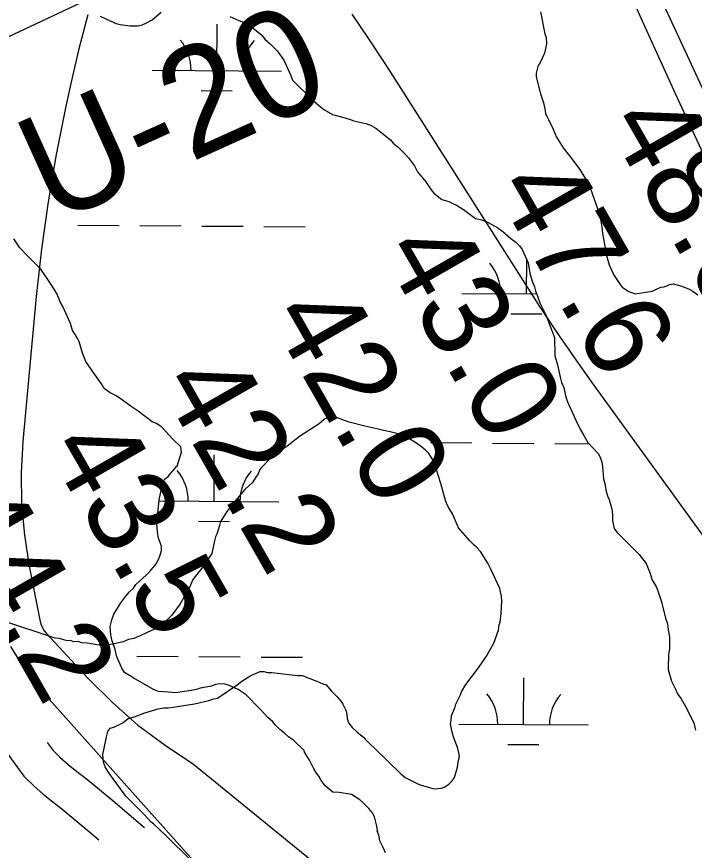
# Model space of a CAD drawing. Extents: x 3172231 to 3210228, y 940198 to 965780.
# Drawn here: x 3188355 to 3188879, y 950157 to 950801 of the extents above; entities that cross this region are included whole.
import ezdxf

# ---------------------------------------------------------------- set-up
doc = ezdxf.new("R2010")
doc.units = 0
for name, color, linetype in [('V-RIVR-RANG', 7, 'Continuous'), ('V-RIVR-RANG-IDEN', 7, 'Continuous'), ('V-ROAD-CNTR', 7, 'Continuous'), ('V-SITE-VEGE', 7, 'Continuous'), ('V-TOPO-MAJR', 7, 'Continuous'), ('V-TOPO-MINR', 7, 'Continuous'), ('V-WETL-SWMP', 7, 'Continuous')]:
    doc.layers.add(name, color=color, linetype=linetype)

msp = doc.modelspace()

# ---------------------------------------------------------------- linework, layer by layer
at = {"layer": 'V-RIVR-RANG'}
msp.add_line((3188285.159, 950755.845), (3189462.372, 951307.359), dxfattribs=at)
at = {"layer": 'V-ROAD-CNTR'}
for points in [[(3188379.01, 950240.383), (3188383.559, 950234.112), (3188388.914, 950229.046), (3188395.301, 950223.428), (3188401.886, 950218.043), (3188409.131, 950212.539), (3188431.275, 950194.143), (3188453.288, 950175.577), (3188454.155, 950174.777)], [(3188346.955, 950233.629), (3188351.119, 950227.74), (3188360.915, 950214.236), (3188368.692, 950206.88), (3188375.891, 950200.546), (3188383.31, 950194.479), (3188390.463, 950189.045), (3188412.019, 950171.139), (3188419.066, 950165.195)]]:
    msp.add_lwpolyline(points, dxfattribs=at)
at = {"layer": 'V-SITE-VEGE'}
for p, q in [((3188760.368, 950804.795), (3188763.839, 950787.852)), ((3188763.839, 950787.852), (3188764.693, 950784.962)), ((3188764.693, 950784.962), (3188765.156, 950779.998)), ((3188765.156, 950779.998), (3188763.565, 950772.942)), ((3188763.565, 950772.942), (3188760.315, 950766.286)), ((3188760.315, 950766.286), (3188758.279, 950762.542)), ((3188758.279, 950762.542), (3188757.083, 950757.562)), ((3188757.083, 950757.562), (3188757.11, 950754.664)), ((3188757.11, 950754.664), (3188760.546, 950741.446)), ((3188760.546, 950741.446), (3188762.682, 950734.43)), ((3188762.682, 950734.43), (3188763.979, 950728.644)), ((3188763.979, 950728.644), (3188764.419, 950725.748)), ((3188764.419, 950725.748), (3188765.681, 950723.69)), ((3188765.681, 950723.69), (3188766.528, 950721.628)), ((3188766.528, 950721.628), (3188770.323, 950714.208)), ((3188770.323, 950714.208), (3188772.867, 950708.023)), ((3188772.867, 950708.023), (3188777.911, 950699.79)), ((3188777.911, 950699.79), (3188782.937, 950693.625)), ((3188782.937, 950693.625), (3188790.904, 950682.935)), ((3188790.904, 950682.935), (3188793.849, 950677.993)), ((3188793.849, 950677.993), (3188795.528, 950675.525)), ((3188795.528, 950675.525), (3188798.901, 950668.93)), ((3188798.901, 950668.93), (3188804.435, 950652.833)), ((3188804.435, 950652.833), (3188805.283, 950650.773)), ((3188805.283, 950650.773), (3188806.567, 950646.228)), ((3188806.567, 950646.228), (3188807.884, 950638.374)), ((3188807.884, 950638.374), (3188808.338, 950633.824)), ((3188808.338, 950633.824), (3188811.4, 950616.463)), ((3188811.4, 950616.463), (3188813.536, 950609.442)), ((3188813.536, 950609.442), (3188816.917, 950602.022)), ((3188816.917, 950602.022), (3188821.96, 950594.203)), ((3188821.96, 950594.203), (3188823.635, 950592.147)), ((3188823.635, 950592.147), (3188828.634, 950588.88)), ((3188846.851, 950589.054), (3188853.448, 950592.012)), ((3188853.448, 950592.012), (3188855.93, 950592.45)), ((3188855.93, 950592.45), (3188860.466, 950594.148)), ((3188860.466, 950594.148), (3188862.946, 950594.586)), ((3188862.946, 950594.586), (3188869.588, 950592.991)), ((3188869.588, 950592.991), (3188875.406, 950590.562)), ((3188828.634, 950588.88), (3188833.621, 950586.859)), ((3188833.621, 950586.859), (3188846.851, 950589.054)), ((3188875.406, 950590.562), (3188878.321, 950588.931)), ((3188878.321, 950588.931), (3188882.073, 950586.068)), ((3188593.542, 950490.212), (3188589.438, 950486.445)), ((3188596.839, 950491.895), (3188593.542, 950490.212)), ((3188603.473, 950491.131), (3188596.839, 950491.895)), ((3188608.873, 950489.112), (3188603.473, 950491.131)), ((3188612.611, 950487.904), (3188608.873, 950489.112)), ((3188585.731, 950484.34), (3188574.209, 950476.781)), ((3188589.438, 950486.445), (3188585.731, 950484.34)), ((3188624.649, 950484.705), (3188612.611, 950487.904)), ((3188633.777, 950482.718), (3188624.649, 950484.705)), ((3188637.928, 950481.516), (3188633.777, 950482.718)), ((3188574.209, 950476.781), (3188565.577, 950470.076)), ((3188644.15, 950480.332), (3188637.928, 950481.516)), ((3188655.357, 950477.539), (3188644.15, 950480.332)), ((3188667.022, 950469.781), (3188655.357, 950477.539)), ((3188565.577, 950470.076), (3188561.874, 950467.557)), ((3188671.612, 950466.096), (3188667.022, 950469.781)), ((3188557.755, 950465.034), (3188551.593, 950460.008)), ((3188561.874, 950467.557), (3188557.755, 950465.034)), ((3188674.119, 950463.635), (3188671.612, 950466.096)), ((3188677.903, 950457.46), (3188674.119, 950463.635)), ((3188551.593, 950460.008), (3188544.619, 950452.903)), ((3188683.443, 950440.535), (3188677.903, 950457.46)), ((3188543.393, 950451.234), (3188542.182, 950447.91)), ((3188544.619, 950452.903), (3188543.393, 950451.234)), ((3188539.729, 950444.576), (3188537.689, 950441.244)), ((3188542.182, 950447.91), (3188539.729, 950444.576)), ((3188537.689, 950441.244), (3188531.942, 950435.809)), ((3188685.596, 950431.86), (3188683.443, 950440.535)), ((3188531.942, 950435.809), (3188522.114, 950424.123)), ((3188687.302, 950426.494), (3188685.596, 950431.86)), ((3188688.995, 950422.37), (3188687.302, 950426.494)), ((3188518.024, 950418.702), (3188515.986, 950415.37)), ((3188522.114, 950424.123), (3188518.024, 950418.702)), ((3188692.358, 950417.016), (3188688.995, 950422.37)), ((3188515.986, 950415.37), (3188513.125, 950411.204)), ((3188697.013, 950406.297), (3188692.358, 950417.016)), ((3188512.329, 950407.882), (3188510.322, 950401.238)), ((3188513.125, 950411.204), (3188512.329, 950407.882)), ((3188705.803, 950396.026), (3188697.013, 950406.297)), ((3188509.099, 950399.158), (3188508.296, 950396.252)), ((3188510.322, 950401.238), (3188509.099, 950399.158)), ((3188508.296, 950396.252), (3188506.32, 950386.296)), ((3188709.148, 950392.745), (3188705.803, 950396.026)), ((3188711.232, 950391.109), (3188709.148, 950392.745)), ((3188506.32, 950386.296), (3188498.558, 950375.044)), ((3188714.163, 950387.822), (3188711.232, 950391.109)), ((3188719.629, 950378.766), (3188714.163, 950387.822)), ((3188498.558, 950375.044), (3188491.601, 950366.283)), ((3188722.156, 950374.233), (3188719.629, 950378.766)), ((3188728.919, 950359.392), (3188722.156, 950374.233)), ((3188491.601, 950366.283), (3188489.176, 950360.049)), ((3188489.176, 950360.049), (3188481.838, 950347.56)), ((3188730.219, 950353.192), (3188728.919, 950359.392)), ((3188481.838, 950347.56), (3188475.295, 950338.803)), ((3188729.929, 950339.94), (3188730.668, 950349.469)), ((3188730.668, 950349.469), (3188730.219, 950353.192)), ((3188475.295, 950338.803), (3188469.142, 950332.534)), ((3188729.163, 950333.308), (3188729.929, 950339.94)), ((3188380.628, 950322.599), (3188348.648, 950333.067)), ((3188464.211, 950328.764), (3188460.084, 950327.068)), ((3188469.142, 950332.534), (3188464.211, 950328.764)), ((3188727.979, 950327.086), (3188728.354, 950331.23)), ((3188728.354, 950331.23), (3188729.163, 950333.308)), ((3188383.538, 950321.385), (3188380.628, 950322.599)), ((3188385.197, 950320.985), (3188383.538, 950321.385)), ((3188451.016, 950322.843), (3188446.066, 950320.725)), ((3188460.084, 950327.068), (3188451.016, 950322.843)), ((3188724.346, 950317.115), (3188727.979, 950327.086)), ((3188388.515, 950320.602), (3188385.197, 950320.985)), ((3188392.664, 950319.398), (3188388.515, 950320.602)), ((3188394.739, 950319.005), (3188392.664, 950319.398)), ((3188396.809, 950319.023), (3188394.739, 950319.005)), ((3188399.715, 950318.221), (3188396.809, 950319.023)), ((3188403.029, 950318.253), (3188399.715, 950318.221)), ((3188405.933, 950317.453), (3188403.029, 950318.253)), ((3188410.076, 950317.078), (3188405.933, 950317.453)), ((3188419.202, 950315.507), (3188410.076, 950317.078)), ((3188424.584, 950315.556), (3188419.202, 950315.507)), ((3188429.544, 950316.431), (3188424.584, 950315.556)), ((3188437.808, 950318.165), (3188429.544, 950316.431)), ((3188441.935, 950319.859), (3188437.808, 950318.165)), ((3188446.066, 950320.725), (3188441.935, 950319.859)), ((3188718.642, 950307.125), (3188724.346, 950317.115)), ((3188712.517, 950297.958), (3188718.642, 950307.125)), ((3188702.7, 950285.033), (3188712.517, 950297.958)), ((3188528.776, 950287.132), (3188536.597, 950292.174)), ((3188536.597, 950292.174), (3188543.608, 950295.138)), ((3188543.608, 950295.138), (3188546.508, 950295.164)), ((3188546.508, 950295.164), (3188549.412, 950294.364)), ((3188549.412, 950294.364), (3188552.725, 950294.394)), ((3188552.725, 950294.394), (3188572.622, 950292.096)), ((3188572.622, 950292.096), (3188576.347, 950292.131)), ((3188576.347, 950292.131), (3188580.087, 950290.509)), ((3188580.087, 950290.509), (3188587.568, 950287.681)), ((3188510.676, 950274.541), (3188526.722, 950285.457)), ((3188526.722, 950285.457), (3188528.776, 950287.132)), ((3188587.568, 950287.681), (3188592.141, 950285.653)), ((3188592.141, 950285.653), (3188594.634, 950284.848)), ((3188594.634, 950284.848), (3188598.82, 950279.919)), ((3188699.438, 950279.618), (3188702.7, 950285.033)), ((3188598.82, 950279.919), (3188603, 950275.819)), ((3188694.973, 950270.052), (3188698.633, 950277.125)), ((3188698.633, 950277.125), (3188699.438, 950279.618)), ((3188476.376, 950267.596), (3188492.912, 950270.236)), ((3188492.912, 950270.236), (3188500.764, 950271.965)), ((3188500.764, 950271.965), (3188504.067, 950272.825)), ((3188504.067, 950272.825), (3188507.782, 950274.101)), ((3188507.782, 950274.101), (3188510.676, 950274.541)), ((3188603, 950275.819), (3188604.675, 950273.763)), ((3188604.675, 950273.763), (3188606.346, 950272.122)), ((3188606.346, 950272.122), (3188607.608, 950270.064)), ((3188607.608, 950270.064), (3188609.715, 950265.943)), ((3188694.578, 950267.977), (3188694.973, 950270.052)), ((3188446.631, 950260.279), (3188454.471, 950263.25)), ((3188454.471, 950263.25), (3188464.795, 950266.247)), ((3188464.795, 950266.247), (3188469.339, 950267.117)), ((3188469.339, 950267.117), (3188472.653, 950267.148)), ((3188472.653, 950267.148), (3188476.376, 950267.596)), ((3188609.715, 950265.943), (3188610.563, 950263.881)), ((3188610.563, 950263.881), (3188611.024, 950258.917)), ((3188691.746, 950260.914), (3188694.578, 950267.977)), ((3188437.564, 950255.64), (3188441.675, 950258.99)), ((3188441.675, 950258.99), (3188446.631, 950260.279)), ((3188611.024, 950258.917), (3188611.884, 950255.611)), ((3188690.976, 950254.696), (3188691.363, 950257.598)), ((3188691.363, 950257.598), (3188691.746, 950260.914)), ((3188426.034, 950248.908), (3188427.666, 950251.407)), ((3188427.666, 950251.407), (3188430.558, 950252.263)), ((3188430.558, 950252.263), (3188437.564, 950255.64)), ((3188611.884, 950255.611), (3188614.817, 950251.913)), ((3188614.817, 950251.913), (3188618.577, 950248.222)), ((3188691.854, 950249.32), (3188690.976, 950254.696)), ((3188424.441, 950242.271), (3188424.832, 950244.757)), ((3188424.832, 950244.757), (3188426.034, 950248.908)), ((3188618.577, 950248.222), (3188623.58, 950244.542)), ((3188623.58, 950244.542), (3188624.838, 950242.897)), ((3188693.136, 950244.777), (3188691.854, 950249.32)), ((3188696.536, 950235.701), (3188693.136, 950244.777)), ((3188422.061, 950231.066), (3188424.441, 950242.271)), ((3188624.838, 950242.897), (3188629.016, 950238.795)), ((3188629.016, 950238.795), (3188631.938, 950236.34)), ((3188422.53, 950225.274), (3188422.061, 950231.066)), ((3188631.938, 950236.34), (3188652.414, 950216.24)), ((3188697.394, 950232.395), (3188696.536, 950235.701)), ((3188697.836, 950229.501), (3188697.394, 950232.395)), ((3188423.806, 950221.559), (3188422.53, 950225.274)), ((3188696.257, 950221.205), (3188697.036, 950226.595)), ((3188697.036, 950226.595), (3188697.836, 950229.501)), ((3188427.167, 950216.208), (3188423.806, 950221.559)), ((3188693.847, 950213.316), (3188696.257, 950221.205)), ((3188428.844, 950214.154), (3188427.167, 950216.208)), ((3188439.752, 950198.935), (3188428.844, 950214.154)), ((3188652.414, 950216.24), (3188655.752, 950213.371)), ((3188655.752, 950213.371), (3188666.154, 950208.087)), ((3188692.213, 950210.815), (3188693.847, 950213.316)), ((3188666.154, 950208.087), (3188668.233, 950207.28)), ((3188668.233, 950207.28), (3188678.194, 950204.475)), ((3188683.988, 950204.944), (3188686.05, 950205.79)), ((3188686.05, 950205.79), (3188689.343, 950207.891)), ((3188689.343, 950207.891), (3188692.213, 950210.815)), ((3188454.376, 950184.578), (3188439.752, 950198.935)), ((3188678.194, 950204.475), (3188683.988, 950204.944)), ((3188459.398, 950178.83), (3188454.376, 950184.578)), ((3188461.485, 950177.193), (3188459.398, 950178.83)), ((3188470.674, 950168.584), (3188461.485, 950177.193)), ((3188490.732, 950148.896), (3188470.674, 950168.584))]:
    msp.add_line(p, q, dxfattribs=at)
at = {"layer": 'V-TOPO-MAJR'}
msp.add_lwpolyline([(3188818.55, 950890.161), (3188903.701, 950706.673), (3188917.3, 950677.732), (3188931.083, 950648.881), (3188945.143, 950620.163), (3188959.387, 950591.534), (3188987.934, 950534.839), (3189009.775, 950491.392), (3189031.575, 950447.925), (3189053.317, 950404.428), (3189075.02, 950360.912), (3189096.296, 950317.197), (3189117.042, 950273.239), (3189136.994, 950228.915), (3189516.871, 949527.552), (3189530.283, 949505.679), (3189543.984, 949483.993), (3189558.119, 949462.587), (3189572.544, 949441.368), (3189951.891, 948895.282)], dxfattribs=at)
at = {"layer": 'V-TOPO-MINR'}
for points in [[(3188818.102, 950844.487), (3188841.309, 950792.749), (3188864.875, 950741.17), (3188892.655, 950681.193)], [(3188410.53, 950802.587), (3188403.635, 950776.137), (3188397.346, 950749.517), (3188393.255, 950730.758), (3188386.042, 950694.528), (3188379.713, 950658.161), (3188374.711, 950621.588), (3188370.594, 950584.877), (3188360.104, 950472.984), (3188358.899, 950448.727), (3188359.103, 950424.545), (3188361.42, 950400.472), (3188365.145, 950376.473), (3188373.684, 950333.878), (3188374.419, 950331.338), (3188375.409, 950328.928), (3188376.783, 950326.715), (3188378.414, 950324.633), (3188410.776, 950289.75), (3188429.505, 950271.21), (3188449.17, 950253.822), (3188470.237, 950238.164), (3188492.239, 950223.658), (3189310.522, 949557.144)], [(3189075.26, 950139.281), (3188799.646, 950519.622), (3188786.117, 950538.66), (3188772.826, 950557.86), (3188759.894, 950577.303), (3188747.199, 950596.908), (3188652.814, 950745.677), (3188640.404, 950764.918), (3188627.805, 950784.032), (3188614.922, 950802.956)], [(3188350.65, 950314.427), (3188360.348, 950298.59), (3188371.754, 950283.624), (3189116.452, 949450.524), (3189128.481, 949437.392), (3189140.717, 949424.462), (3189153.265, 949411.833), (3189166.02, 949399.405), (3189181.307, 949384.869), (3189186.593, 949379.879), (3189191.902, 949374.915), (3189197.246, 949369.99), (3189202.615, 949365.09), (3189207.88, 949360.094), (3189212.983, 949354.946), (3189217.845, 949349.568), (3189222.546, 949344.038), (3189258.278, 949299.984), (3189261.644, 949295.826), (3189265.004, 949291.662), (3189268.356, 949287.492), (3189271.701, 949283.317), (3190177.18, 948464.824)]]:
    msp.add_lwpolyline(points, dxfattribs=at)
at = {"layer": 'V-WETL-SWMP'}
for p, q in [((3188510.281, 950759.363), (3188510.526, 950795.362)), ((3188460.282, 950759.703), (3188560.28, 950759.022)), ((3188498.176, 950744.014), (3188522.176, 950743.85)), ((3188402.622, 950640.022), (3188434.622, 950639.804)), ((3188450.621, 950639.695), (3188482.621, 950639.477)), ((3188498.62, 950639.368), (3188530.619, 950639.151)), ((3188546.619, 950639.042), (3188578.618, 950638.824)), ((3188749.585, 950586.917), (3188749.766, 950613.53)), ((3188699.586, 950587.257), (3188757.588, 950586.862)), ((3188737.48, 950571.568), (3188761.48, 950571.404)), ((3188675.393, 950471.987), (3188707.392, 950471.769)), ((3188723.392, 950471.66), (3188755.391, 950471.443)), ((3188771.391, 950471.334), (3188797.931, 950471.153)), ((3188508.017, 950426.695), (3188508.262, 950462.695)), ((3188465.655, 950426.984), (3188558.015, 950426.355)), ((3188495.912, 950411.347), (3188519.911, 950411.183)), ((3188448.357, 950307.028), (3188480.356, 950306.81)), ((3188496.356, 950306.701), (3188528.355, 950306.483)), ((3188544.354, 950306.374), (3188576.354, 950306.157)), ((3188747.32, 950254.25), (3188747.565, 950290.249)), ((3188697.321, 950254.59), (3188797.319, 950253.909)), ((3188735.215, 950238.901), (3188759.215, 950238.737))]:
    msp.add_line(p, q, dxfattribs=at)
for points in [[(3188420.003, 950801.573), (3188428.322, 950797.51), (3188432.478, 950795.893), (3188435.383, 950795.092), (3188442.847, 950793.92), (3188449.472, 950793.981), (3188452.362, 950794.837), (3188455.249, 950796.106), (3188460.194, 950798.636), (3188467.178, 950804.498)], [(3188520.207, 950801.267), (3188527.277, 950798.021), (3188530.6, 950796.81), (3188533.514, 950795.181), (3188536.431, 950793.137), (3188539.345, 950791.508), (3188545.188, 950786.594), (3188547.285, 950783.716), (3188551.46, 950780.028), (3188556.892, 950774.696), (3188560.247, 950770.173), (3188562.348, 950766.88), (3188567.421, 950755.748), (3188568.698, 950752.033), (3188584.577, 950736.447), (3188588.752, 950732.76), (3188592.924, 950729.486), (3188599.587, 950725.408), (3188606.64, 950723.818), (3188609.964, 950722.607), (3188612.87, 950721.806), (3188616.194, 950720.595), (3188625.322, 950718.61), (3188629.477, 950716.992), (3188633.223, 950714.957), (3188644.486, 950705.953), (3188646.58, 950703.488), (3188650.337, 950700.211), (3188654.516, 950696.109), (3188658.28, 950692.004), (3188662.893, 950685.836), (3188665.419, 950681.305), (3188667.934, 950678.016), (3188671.703, 950673.497), (3188675.901, 950667.325), (3188677.995, 950664.86), (3188684.251, 950659.95), (3188689.649, 950658.344), (3188692.563, 950656.715), (3188695.472, 950655.5), (3188700.886, 950652.238), (3188710.06, 950645.285), (3188715.04, 950644.089), (3188720.027, 950642.066), (3188727.518, 950637.995), (3188731.271, 950635.132), (3188737.532, 950629.807), (3188741.285, 950626.944), (3188744.211, 950624.073), (3188746.308, 950621.194), (3188750.959, 950610.886), (3188752.274, 950603.031), (3188753.988, 950596.837), (3188755.687, 950592.298), (3188756.542, 950589.407), (3188758.237, 950585.283), (3188759.943, 950579.916), (3188764.582, 950570.85), (3188771.373, 950553.109), (3188771.504, 950539.032), (3188773.64, 950532.013), (3188775.807, 950521.682), (3188776.666, 950518.378), (3188778.357, 950514.667), (3188779.661, 950508.054), (3188781.359, 950503.516), (3188787.701, 950489.497), (3188791.079, 950482.49), (3188794.024, 950477.548), (3188796.972, 950472.193), (3188804.92, 950463.572), (3188806.603, 950460.69), (3188807.88, 950456.975), (3188808.325, 950453.667), (3188809.245, 950443.738), (3188810.104, 950440.433), (3188810.979, 950435.473), (3188812.263, 950430.93), (3188813.533, 950428.044), (3188815.672, 950420.611), (3188816.125, 950416.474), (3188816.171, 950411.506), (3188817.468, 950405.722), (3188819.565, 950402.843), (3188828.344, 950393.815)], [(3188536.312, 950273.91), (3188532.969, 950277.191), (3188526.72, 950281.273), (3188519.237, 950284.516), (3188516.331, 950285.317), (3188512.601, 950285.696), (3188509.293, 950285.251), (3188505.992, 950283.978), (3188497.313, 950282.241), (3188494.423, 950281.386), (3188490.291, 950280.519), (3188478.299, 950278.751), (3188472.499, 950279.111), (3188465.039, 950279.869), (3188461.715, 950281.08), (3188446.729, 950289.635), (3188442.566, 950292.081), (3188438.817, 950294.53), (3188436.716, 950297.823), (3188432.908, 950306.483), (3188431.612, 950312.267), (3188429.568, 950318.212), (3188429.058, 950319.697), (3188428.195, 950323.415), (3188427.72, 950330.035), (3188428.915, 950335.015), (3188430.529, 950339.585), (3188436.068, 950348.137), (3188439.924, 950353.337), (3188442.791, 950356.676), (3188445.662, 950359.601), (3188447.705, 950362.518), (3188455.506, 950369.63), (3188458.377, 950372.556), (3188463.291, 950378.398), (3188464.92, 950381.312), (3188466.135, 950384.222), (3188467.334, 950388.787), (3188467.303, 950392.1), (3188465.175, 950398.29), (3188464.305, 950402.837), (3188463.829, 950409.457), (3188465.729, 950427.694), (3188467.706, 950437.649), (3188468.507, 950440.555), (3188469.718, 950443.879), (3188472.597, 950445.976), (3188476.284, 950450.151), (3188479.148, 950453.905), (3188479.562, 950453.908), (3188482.773, 950464.704), (3188482.321, 950468.84), (3188476.052, 950474.992), (3188467.687, 950484.024), (3188463.52, 950486.883), (3188460.196, 950488.094), (3188449.354, 950496.274), (3188443.937, 950499.95), (3188437.266, 950504.856), (3188432.267, 950508.122), (3188427.69, 950510.564), (3188423.104, 950513.833), (3188421, 950517.54), (3188415.966, 950524.532), (3188408.831, 950534.817), (3188406.288, 950541.004), (3188403.719, 950550.089), (3188400.771, 950555.444), (3188398.67, 950558.737), (3188396.963, 950564.104), (3188393.578, 950571.939), (3188391.043, 950577.298), (3188389.36, 950580.181), (3188386.396, 950587.192), (3188382.19, 950594.192), (3188374.212, 950606.125), (3188364.183, 950615.969), (3188357.91, 950622.535), (3188353.291, 950629.531)], [(3188828.344, 950393.815), (3188836.702, 950385.612), (3188842.15, 950378.624), (3188845.122, 950370.785), (3188846.824, 950365.832), (3188849.769, 950360.891), (3188851.463, 950356.766), (3188853.599, 950349.747), (3188857.457, 950335.705), (3188858.734, 950331.991), (3188859.19, 950327.441), (3188860.069, 950322.066), (3188860.154, 950312.958), (3188859.372, 950307.982), (3188859.403, 950304.669), (3188859.02, 950301.353), (3188859.062, 950296.799), (3188861.632, 950287.714), (3188864.584, 950281.945), (3188866.279, 950277.82), (3188869.212, 950274.121), (3188872.16, 950268.766), (3188878.908, 950255.579), (3188880.204, 950249.794)], [(3188640.521, 950155.221), (3188638.826, 950159.346), (3188636.296, 950164.291), (3188635.425, 950168.837), (3188634.156, 950171.724), (3188634.574, 950171.314), (3188633.696, 950176.688), (3188631.982, 950182.883), (3188630.295, 950186.18), (3188627.779, 950189.469), (3188623.183, 950193.98), (3188620.679, 950196.027), (3188614.43, 950200.11), (3188604.892, 950201.677), (3188599.92, 950202.044), (3188594.078, 950206.958), (3188590.723, 950211.482), (3188589.04, 950214.364), (3188586.525, 950217.653), (3188584.842, 950220.536), (3188581.885, 950226.719), (3188578.101, 950232.895), (3188577.676, 950234.133), (3188569.736, 950241.926), (3188565.568, 950244.785), (3188562.643, 950247.656), (3188558.89, 950250.52), (3188555.547, 950253.801), (3188553.454, 950256.266), (3188549.696, 950259.543), (3188544.256, 950265.703), (3188539.659, 950270.215), (3188536.312, 950273.91)]]:
    msp.add_lwpolyline(points, dxfattribs=at)
for centre, start, end in [((3188455.043, 950760.214), 358.838165, 40.381824), ((3188565.526, 950759.461), 138.838162, 180.381821), ((3188694.346, 950587.768), 358.838165, 40.381824), ((3188452.778, 950427.546), 358.838165, 40.381824), ((3188563.261, 950426.794), 138.838162, 180.381821), ((3188692.082, 950255.1), 358.838165, 40.381824), ((3188802.565, 950254.348), 138.838162, 180.381821)]:
    msp.add_arc(centre, 35.246, start, end, dxfattribs=at)

# ---------------------------------------------------------------- texts
at = {"layer": 'V-RIVR-RANG'}
for s, p in [('48.6', (3188810.423, 950718.645)), ('47.6', (3188723.761, 950668.747)), ('43.0', (3188636.576, 950619.765)), ('42.0', (3188549.915, 950569.867)), ('42.2', (3188464.694, 950517.451)), ('43.5', (3188378.033, 950467.553)), ('44.2', (3188291.371, 950417.655))]:
    msp.add_text(s, height=67, rotation=299.788326, dxfattribs=at).set_placement(p)
at = {"layer": 'V-RIVR-RANG-IDEN'}
msp.add_text('U-20', height=83, rotation=24.319915, dxfattribs=at).set_placement((3188382.969, 950640.063))

doc.saveas('drawing.dxf')
